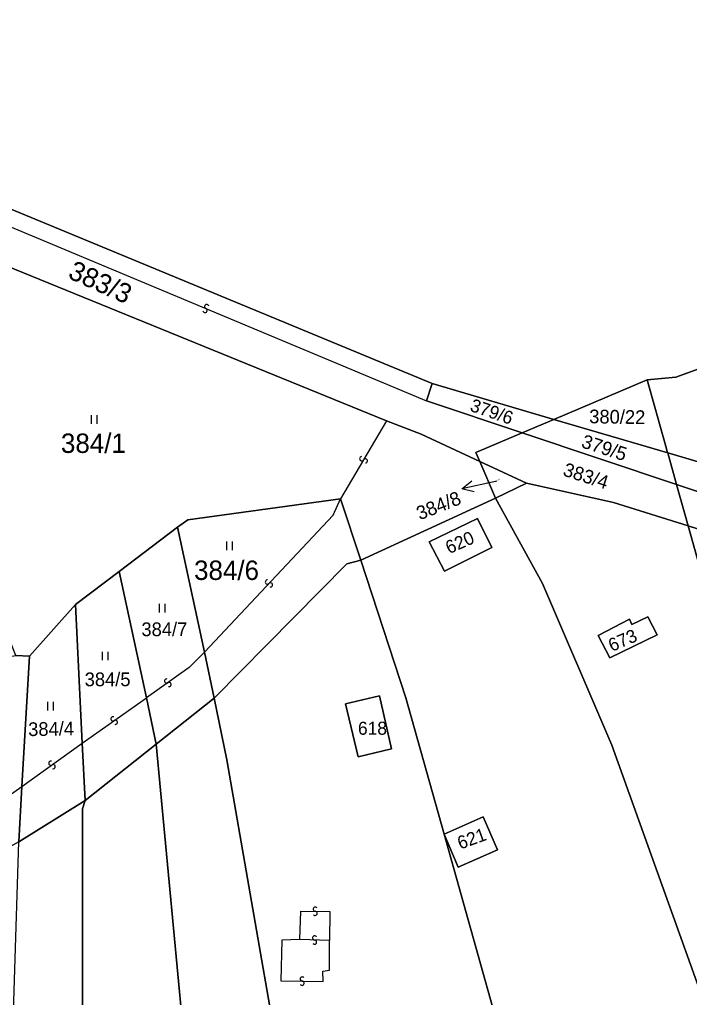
# Model space of a CAD drawing. Extents: x -600309 to -598967, y -1161267 to -1160292.
# Drawn here: x -599774.9 to -599716.3, y -1160805.5 to -1160719.9 of the extents above; entities that cross this region are included whole.
import ezdxf

# ---------------------------------------------------------------- set-up
doc = ezdxf.new("R2010")
doc.units = 0
for name, color, linetype in [('Level 1', 7, 'Continuous'), ('Level 13', 7, 'Continuous'), ('Level 3', 7, 'Continuous'), ('Level 4', 7, 'Continuous'), ('Level 5', 7, 'Continuous'), ('Level 57', 7, 'Continuous'), ('Level 60', 7, 'Continuous')]:
    doc.layers.add(name, color=color, linetype=linetype)

msp = doc.modelspace()

# ---------------------------------------------------------------- linework, layer by layer
at = {"layer": 'Level 1'}
for points in [[(-599738.79, -1160751.73), (-599783.62, -1160733.18), (-599819.89, -1160690.7)], [(-599742.8, -1160755), (-599779.99, -1160739.86), (-599783.33, -1160737.73), (-599788.05, -1160733.72), (-599790.83, -1160730.52)], [(-599719.97, -1160751.4), (-599717.45, -1160751.17), (-599704.13, -1160746.31), (-599701.96, -1160753.49), (-599695.56, -1160752.94)], [(-599738.79, -1160751.73), (-599739.29, -1160753.24)], [(-599738.79, -1160751.73), (-599728.14, -1160754.87)], [(-599728.14, -1160754.87), (-599719.97, -1160751.4)], [(-599719.97, -1160751.4), (-599718.36, -1160757.12), (-599718.21, -1160757.67), (-599718.17, -1160757.8)], [(-599739.29, -1160753.24), (-599730.92, -1160756.04)], [(-599742.8, -1160755), (-599739.76, -1160756.17), (-599734.63, -1160758.55)], [(-599730.92, -1160756.04), (-599728.14, -1160754.87)], [(-599728.14, -1160754.87), (-599718.17, -1160757.8)], [(-599734.63, -1160758.55), (-599734.97, -1160757.76), (-599730.92, -1160756.04)], [(-599717.4, -1160760.57), (-599730.92, -1160756.04)], [(-599730.53, -1160760.44), (-599734.63, -1160758.55)], [(-599733.24, -1160761.76), (-599734.63, -1160758.55)], [(-599718.17, -1160757.8), (-599717.4, -1160760.57)], [(-599714.51, -1160758.88), (-599718.17, -1160757.8)], [(-599730.53, -1160760.44), (-599733.24, -1160761.76)], [(-599730.53, -1160760.44), (-599722.91, -1160762.15), (-599716.38, -1160764.19)], [(-599717.4, -1160760.57), (-599716.38, -1160764.19)], [(-599713.64, -1160761.83), (-599717.4, -1160760.57)], [(-599746.82, -1160761.81), (-599760.2, -1160763.67), (-599761.09, -1160764.29)], [(-599745.05, -1160767.2), (-599746.82, -1160761.81)], [(-599733.24, -1160761.76), (-599745.05, -1160767.2)], [(-599733.24, -1160761.76), (-599729.14, -1160769.24), (-599723.06, -1160783.39), (-599710.25, -1160819.11), (-599700.44, -1160852.81), (-599699.39, -1160863.35)], [(-599739.05, -1160765.58), (-599734.83, -1160763.55), (-599733.57, -1160766.07), (-599737.73, -1160768.15), (-599739.05, -1160765.58)], [(-599761.09, -1160764.29), (-599766.2, -1160768.17)], [(-599761.09, -1160764.29), (-599758.75, -1160775.23)], [(-599716.38, -1160764.19), (-599715.55, -1160764.45), (-599712.54, -1160765.57)], [(-599716.38, -1160764.19), (-599710.89, -1160783.75), (-599709.25, -1160789.42), (-599699.68, -1160817.5), (-599689.69, -1160850.57), (-599683.98, -1160869.95), (-599679.47, -1160892.29)], [(-599745.05, -1160767.2), (-599746.26, -1160767.5), (-599757.89, -1160779.26)], [(-599745.05, -1160767.2), (-599741.11, -1160779.23), (-599737.76, -1160791.16)], [(-599770.02, -1160771.07), (-599766.2, -1160768.17)], [(-599766.2, -1160768.17), (-599763.83, -1160779.24)], [(-599770.02, -1160771.07), (-599774.07, -1160775.6)], [(-599770.02, -1160771.07), (-599769.46, -1160783.22)], [(-599724.26, -1160773.78), (-599721.52, -1160772.36), (-599721.3, -1160772.83), (-599719.92, -1160772.16), (-599719.1, -1160773.73), (-599723.24, -1160775.74), (-599724.26, -1160773.78)], [(-599774.07, -1160775.6), (-599775.25, -1160775.52)], [(-599774.07, -1160775.6), (-599774.72, -1160787)], [(-599758.75, -1160775.23), (-599757.89, -1160779.26)], [(-599746.38, -1160779.76), (-599743.41, -1160779.07), (-599742.35, -1160783.7), (-599745.28, -1160784.41), (-599746.38, -1160779.76)], [(-599763.83, -1160779.24), (-599762.97, -1160783.29)], [(-599757.89, -1160779.26), (-599762.97, -1160783.29)], [(-599757.89, -1160779.26), (-599756.78, -1160784.68), (-599750.21, -1160822.37), (-599746.28, -1160866.11), (-599746.71, -1160877.62)], [(-599769.46, -1160783.22), (-599769.19, -1160788.24)], [(-599769.19, -1160788.24), (-599762.97, -1160783.29)], [(-599762.97, -1160783.29), (-599759.54, -1160819.53), (-599758.28, -1160846.61), (-599759.03, -1160876.57)], [(-599774.72, -1160787), (-599774.99, -1160791.85)], [(-599769.19, -1160788.24), (-599774.99, -1160791.85)], [(-599769.19, -1160788.24), (-599769.43, -1160788.97), (-599769.39, -1160832.11), (-599770.12, -1160869.39)], [(-599737.76, -1160791.16), (-599734.34, -1160789.66), (-599733.07, -1160792.54), (-599736.52, -1160794.05), (-599737.76, -1160791.16)], [(-599737.76, -1160791.16), (-599730.3, -1160817.74), (-599722.41, -1160863.39)]]:
    msp.add_lwpolyline(points, dxfattribs=at)
at = {"layer": 'Level 13'}
for centre, start, end in [((-599758.547, -1160744.99), 14.68031, 246.77831), ((-599758.692, -1160745.329), 194.46586, 67.05586), ((-599744.968, -1160758.306), 96.60457, 329.19457), ((-599744.652, -1160758.495), 276.81903, 148.91702), ((-599753.233, -1160769.102), 84.09503, 316.19302), ((-599752.967, -1160769.357), 263.88057, 136.47057), ((-599762.056, -1160777.769), 72.40585, 304.99585), ((-599761.845, -1160778.072), 252.62031, 124.71831), ((-599766.745, -1160781.078), 72.63026, 304.72826), ((-599766.534, -1160781.381), 252.41581, 125.00581), ((-599772.196, -1160784.959), 73.07494, 305.17293), ((-599771.983, -1160785.26), 252.86048, 125.45048), ((-599749.035, -1160797.736), 36.47405, 268.57205), ((-599749.044, -1160798.104), 216.25959, 88.84959), ((-599749.083, -1160800.256), 35.19088, 267.78088), ((-599749.098, -1160800.624), 215.40533, 87.50333), ((-599750.184, -1160803.856), 36.1341, 268.23209), ((-599750.195, -1160804.224), 215.91964, 88.50964)]:
    msp.add_arc(centre, 0.184, start, end, dxfattribs=at)
at = {"layer": 'Level 3'}
for points in [[(-599814.62, -1160702.42), (-599804.76, -1160710.4), (-599800.02, -1160715.09), (-599786.17, -1160731.52), (-599782.68, -1160734.74), (-599777.96, -1160737.07), (-599739.29, -1160753.24)], [(-599742.8, -1160755), (-599746.82, -1160761.81)], [(-599758.75, -1160775.23), (-599747.46, -1160763.24), (-599746.82, -1160761.81)], [(-599758.75, -1160775.23), (-599760.08, -1160776.59), (-599763.83, -1160779.24)], [(-599769.46, -1160783.22), (-599763.83, -1160779.24)], [(-599774.72, -1160787), (-599769.46, -1160783.22)], [(-599786.71, -1160790.28), (-599776.86, -1160788.48), (-599774.72, -1160787)], [(-599750.4, -1160800.4), (-599750.31, -1160797.9), (-599747.76, -1160797.94), (-599747.78, -1160800.49)], [(-599750.4, -1160800.4), (-599751.96, -1160800.45), (-599752.04, -1160804), (-599748.34, -1160804.08), (-599748.36, -1160803.16), (-599747.8, -1160803.08), (-599747.78, -1160800.49)], [(-599747.78, -1160800.49), (-599750.4, -1160800.4)]]:
    msp.add_lwpolyline(points, dxfattribs=at)
at = {"layer": 'Level 5'}
for p, q in [((-599768.64, -1160755.255), (-599768.64, -1160754.504)), ((-599768.14, -1160755.255), (-599768.14, -1160754.504)), ((-599756.78, -1160766.315), (-599756.78, -1160765.564)), ((-599756.28, -1160766.315), (-599756.28, -1160765.564)), ((-599762.69, -1160771.765), (-599762.69, -1160771.014)), ((-599762.19, -1160771.765), (-599762.19, -1160771.014)), ((-599767.66, -1160775.955), (-599767.66, -1160775.204)), ((-599767.16, -1160775.955), (-599767.16, -1160775.204)), ((-599772.47, -1160780.345), (-599772.47, -1160779.594)), ((-599771.97, -1160780.345), (-599771.97, -1160779.594))]:
    msp.add_line(p, q, dxfattribs=at)
at = {"layer": 'Level 57'}
for p, q in [((-599733.263, -1160760.293), (-599736.19, -1160760.95)), ((-599733.16, -1160760.27), (-599733.263, -1160760.293))]:
    msp.add_line(p, q, dxfattribs=at)
msp.add_lwpolyline([(-599735.105, -1160761.219), (-599736.19, -1160760.95), (-599735.324, -1160760.243)], dxfattribs=at)
at = {"layer": 'Level 60'}
for points in [[(-599738.79, -1160751.73), (-599739.29, -1160753.24), (-599730.92, -1160756.04), (-599734.97, -1160757.76), (-599734.63, -1160758.55), (-599739.76, -1160756.17), (-599742.8, -1160755), (-599779.99, -1160739.86), (-599783.33, -1160737.73), (-599788.05, -1160733.72), (-599790.83, -1160730.52), (-599801.71, -1160717.92), (-599806.7, -1160712.83), (-599817.3, -1160705.43), (-599814.62, -1160702.42), (-599819.16, -1160698.48), (-599819.97, -1160697.81), (-599820.83, -1160696.17), (-599821.16, -1160694.35), (-599820.89, -1160692.52), (-599820.06, -1160690.89), (-599819.89, -1160690.7), (-599783.62, -1160733.18)], [(-599779.99, -1160739.86), (-599742.8, -1160755), (-599739.76, -1160756.17), (-599734.63, -1160758.55), (-599733.24, -1160761.76), (-599745.05, -1160767.2), (-599746.82, -1160761.81), (-599760.2, -1160763.67), (-599761.09, -1160764.29), (-599766.2, -1160768.17), (-599770.02, -1160771.07), (-599774.07, -1160775.6), (-599775.25, -1160775.52), (-599779.53, -1160764.82), (-599790.83, -1160730.52), (-599788.05, -1160733.72), (-599783.33, -1160737.73)], [(-599705.5, -1160761.54), (-599707.42, -1160760.97), (-599714.51, -1160758.88), (-599718.17, -1160757.8), (-599718.21, -1160757.67), (-599718.36, -1160757.12), (-599719.97, -1160751.4), (-599717.45, -1160751.17), (-599704.13, -1160746.31), (-599701.96, -1160753.49), (-599695.56, -1160752.94), (-599691.7, -1160761.62), (-599687.33, -1160772.26)], [(-599739.29, -1160753.24), (-599738.79, -1160751.73), (-599728.14, -1160754.87), (-599730.92, -1160756.04)], [(-599718.17, -1160757.8), (-599728.14, -1160754.87), (-599719.97, -1160751.4), (-599718.36, -1160757.12), (-599718.21, -1160757.67)], [(-599728.14, -1160754.87), (-599718.17, -1160757.8), (-599717.4, -1160760.57), (-599730.92, -1160756.04)], [(-599722.91, -1160762.15), (-599730.53, -1160760.44), (-599734.63, -1160758.55), (-599734.97, -1160757.76), (-599730.92, -1160756.04), (-599717.4, -1160760.57), (-599716.38, -1160764.19)], [(-599730.53, -1160760.44), (-599733.24, -1160761.76), (-599734.63, -1160758.55)], [(-599717.4, -1160760.57), (-599718.17, -1160757.8), (-599714.51, -1160758.88), (-599713.64, -1160761.83)], [(-599699.21, -1160864.94), (-599699.39, -1160863.35), (-599700.44, -1160852.81), (-599710.25, -1160819.11), (-599723.06, -1160783.39), (-599729.14, -1160769.24), (-599733.24, -1160761.76), (-599730.53, -1160760.44), (-599722.91, -1160762.15), (-599716.38, -1160764.19), (-599710.89, -1160783.75), (-599709.25, -1160789.42), (-599699.68, -1160817.5), (-599689.69, -1160850.57), (-599683.98, -1160869.95), (-599679.47, -1160892.29), (-599679.2, -1160893.91), (-599686.33, -1160894.81), (-599696.45, -1160896.09), (-599696.65, -1160893.67), (-599696.9, -1160891.08), (-599698.24, -1160876.32), (-599698.61, -1160871.78), (-599699.05, -1160867.18)], [(-599715.55, -1160764.45), (-599716.38, -1160764.19), (-599717.4, -1160760.57), (-599713.64, -1160761.83), (-599712.54, -1160765.57)], [(-599760.2, -1160763.67), (-599746.82, -1160761.81), (-599745.05, -1160767.2), (-599746.26, -1160767.5), (-599757.89, -1160779.26), (-599758.75, -1160775.23), (-599761.09, -1160764.29)], [(-599699.39, -1160863.35), (-599722.41, -1160863.39), (-599730.3, -1160817.74), (-599737.76, -1160791.16), (-599736.52, -1160794.05), (-599733.07, -1160792.54), (-599734.34, -1160789.66), (-599737.76, -1160791.16), (-599741.11, -1160779.23), (-599745.05, -1160767.2), (-599733.24, -1160761.76), (-599729.14, -1160769.24), (-599723.06, -1160783.39), (-599710.25, -1160819.11), (-599700.44, -1160852.81)], [(-599734.83, -1160763.55), (-599739.05, -1160765.58), (-599737.73, -1160768.15), (-599733.57, -1160766.07)], [(-599739.05, -1160765.58), (-599734.83, -1160763.55), (-599733.57, -1160766.07), (-599737.73, -1160768.15)], [(-599761.09, -1160764.29), (-599758.75, -1160775.23), (-599757.89, -1160779.26), (-599762.97, -1160783.29), (-599763.83, -1160779.24), (-599766.2, -1160768.17)], [(-599673.46, -1160891.53), (-599679.47, -1160892.29), (-599683.98, -1160869.95), (-599689.69, -1160850.57), (-599699.68, -1160817.5), (-599709.25, -1160789.42), (-599710.89, -1160783.75), (-599716.38, -1160764.19), (-599715.55, -1160764.45), (-599712.54, -1160765.57), (-599705.69, -1160788.09), (-599696.51, -1160816.41), (-599679.15, -1160868.37)], [(-599722.62, -1160879.05), (-599746.71, -1160877.62), (-599746.28, -1160866.11), (-599750.21, -1160822.37), (-599756.78, -1160784.68), (-599757.89, -1160779.26), (-599746.26, -1160767.5), (-599745.05, -1160767.2), (-599741.11, -1160779.23), (-599737.76, -1160791.16), (-599730.3, -1160817.74), (-599722.41, -1160863.39)], [(-599769.46, -1160783.22), (-599770.02, -1160771.07), (-599766.2, -1160768.17), (-599763.83, -1160779.24), (-599762.97, -1160783.29), (-599769.19, -1160788.24)], [(-599774.07, -1160775.6), (-599770.02, -1160771.07), (-599769.46, -1160783.22), (-599769.19, -1160788.24), (-599774.99, -1160791.85), (-599774.72, -1160787)], [(-599721.52, -1160772.36), (-599724.26, -1160773.78), (-599723.24, -1160775.74), (-599719.1, -1160773.73), (-599719.92, -1160772.16), (-599721.3, -1160772.83)], [(-599724.26, -1160773.78), (-599721.52, -1160772.36), (-599721.3, -1160772.83), (-599719.92, -1160772.16), (-599719.1, -1160773.73), (-599723.24, -1160775.74)], [(-599775.25, -1160775.52), (-599774.07, -1160775.6), (-599774.72, -1160787), (-599774.99, -1160791.85), (-599787.84, -1160798.99), (-599786.71, -1160790.28), (-599786.02, -1160777.23)], [(-599743.41, -1160779.07), (-599746.38, -1160779.76), (-599745.28, -1160784.41), (-599742.35, -1160783.7)], [(-599746.38, -1160779.76), (-599743.41, -1160779.07), (-599742.35, -1160783.7), (-599745.28, -1160784.41)], [(-599757.89, -1160779.26), (-599756.78, -1160784.68), (-599750.21, -1160822.37), (-599746.28, -1160866.11), (-599746.71, -1160877.62), (-599759.03, -1160876.57), (-599758.28, -1160846.61), (-599759.54, -1160819.53), (-599762.97, -1160783.29)], [(-599769.43, -1160788.97), (-599769.19, -1160788.24), (-599762.97, -1160783.29), (-599759.54, -1160819.53), (-599758.28, -1160846.61), (-599759.03, -1160876.57), (-599770.39, -1160875.6), (-599770.12, -1160869.39), (-599769.39, -1160832.11)], [(-599770.39, -1160875.6), (-599777.87, -1160874.77), (-599777.42, -1160868.1), (-599774.99, -1160791.85), (-599769.19, -1160788.24), (-599769.43, -1160788.97), (-599769.39, -1160832.11), (-599770.12, -1160869.39)], [(-599737.76, -1160791.16), (-599734.34, -1160789.66), (-599733.07, -1160792.54), (-599736.52, -1160794.05)]]:
    msp.add_lwpolyline(points, close=True, dxfattribs=at)
msp.add_lwpolyline([(-599701.59, -1160717.22), (-599696.95, -1160733.23), (-599689.19, -1160730.99), (-599688.88, -1160732.07), (-599697.66, -1160734.6), (-599693.52, -1160749.01), (-599695.56, -1160752.94), (-599701.96, -1160753.49), (-599704.13, -1160746.31), (-599717.45, -1160751.17), (-599719.97, -1160751.4), (-599728.14, -1160754.87), (-599738.79, -1160751.73), (-599783.62, -1160733.18)], dxfattribs=at)

# ---------------------------------------------------------------- texts
at = {"layer": 'Level 4'}
for s, height, rotation, p in [('383/3', 1.7, 335.7, (-599770.79, -1160742.45)), ('379/6', 1.14, 341.1, (-599735.56, -1160754.1)), ('380/22', 1.2, 359.1, (-599725.05, -1160755.2)), ('379/5', 1.2, 342, (-599725.81, -1160757.29)), ('383/4', 1.2, 342, (-599727.42, -1160759.76)), ('384/8', 0.1, 21.6, (-599733.16, -1160760.27)), ('620', 1.14, 23.75991, (-599737.316, -1160766.667)), ('673', 1.14, 23.41449, (-599723.06, -1160775.228)), ('384/4', 1.2, 0.9, (-599774.17, -1160782.59)), ('621', 1.14, 19.86255, (-599736.339, -1160792.526))]:
    msp.add_text(s, height=height, rotation=rotation, dxfattribs=at).set_placement(p)
for s, height, p in [('384/1', 1.7, (-599771.31, -1160757.8)), ('384/6', 1.7, (-599759.65, -1160768.92)), ('384/7', 1.2, (-599764.26, -1160773.84)), ('384/5', 1.2, (-599769.23, -1160778.22)), ('618', 1.14, (-599745.297, -1160782.47))]:
    msp.add_text(s, height=height, dxfattribs=at).set_placement(p)
at = {"layer": 'Level 57'}
msp.add_text('384/8', height=1.2, rotation=21.6, dxfattribs=at).set_placement((-599739.884, -1160763.703))

doc.saveas('drawing.dxf')
